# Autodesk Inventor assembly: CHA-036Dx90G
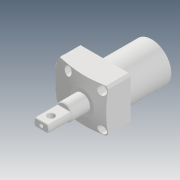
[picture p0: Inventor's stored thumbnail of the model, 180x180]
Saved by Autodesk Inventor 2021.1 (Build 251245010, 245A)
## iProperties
Created: 2019-12
Part Number: CHA-036Dx90G
Description: STEP AP203
Document SubType Name: Assembly
Designer: user
Title: CHA-036Dx90G.STEP
Revision Number: ÈÎºÎ
Sending System: SolidWorks 2017
Preprocessor: SwSTEP 2.0
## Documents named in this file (4)
- D:\Vault_2016\Projekty\Clamptek\Hydraulic\CHA\CHA\CHA-036\Inventor\CHA-036Dx90G\CHA-036Dx90G.iam
- D:\Vault_2016\Projekty\Clamptek\Hydraulic\CHA\CHA\CHA-036\Inventor\CHA-036Dx90G\CHA-036C±¾Ìå_1.ipt
- D:\Vault_2016\Projekty\Clamptek\Hydraulic\CHA\CHA\CHA-036\Inventor\CHA-036Dx90G\G1-8¶ÂÍ·.ipt
- D:\Vault_2016\Projekty\Clamptek\Hydraulic\CHA\CHA\CHA-036\Inventor\CHA-036Dx90G\CHA-036D(Ë«±Û£©»îÈû¸Ë_1.ipt
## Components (4 placed, 4 different names)
1. CHA-036C±¾Ìå_1_1
2. G1-8¶ÂÍ·_2
3. CHA-036D(Ë«±Û£©»îÈû¸Ë_1_3
4. G1-8¶ÂÍ·_4
